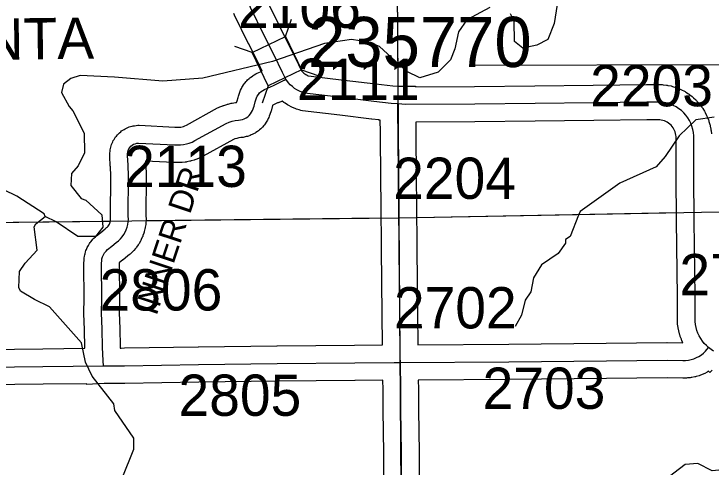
# Model space of a CAD drawing. Extents: x 23.6 to 68.7, y -63 to -29.
# Drawn here: x 41.141 to 42.324, y -56.084 to -55.315 of the extents above; entities that cross this region are included whole.
import ezdxf

# ---------------------------------------------------------------- set-up
doc = ezdxf.new("R2010")
doc.units = 0
for name, color, linetype in [('tdCoDirctArrow', 7, 'Continuous'), ('tdCoHydroRiver', 7, 'Continuous'), ('tdCoSecRdNmbr', 7, 'Continuous'), ('tdCoSecRdTxt', 7, 'Continuous'), ('tdCoSecRteBand', 7, 'Continuous'), ('tdCoSecRteCL', 7, 'Continuous'), ('tdCoSectLine', 7, 'Continuous'), ('tdCoSectLinePart', 7, 'Continuous'), ('tdCoStrucSec', 7, 'Continuous'), ('tdCoStrucSecFHWANum', 7, 'Continuous'), ('tdCoSurfGravel', 7, 'Continuous'), ('tdCoUnicrpTwnTxt', 7, 'Continuous')]:
    doc.layers.add(name, color=color, linetype=linetype)

msp = doc.modelspace()

# ---------------------------------------------------------------- linework, layer by layer
at = {"layer": 'tdCoDirctArrow'}
msp.add_lwpolyline([(41.919, -55.4023), (42.3403, -55.4012)], dxfattribs=at)
at = {"layer": 'tdCoHydroRiver'}
for points in [[(42.0696, -55.2557), (42.0577, -55.3316), (42.0469, -55.3586), (42.028, -55.3682), (42.0044, -55.3732), (41.9901, -55.3623), (41.9898, -55.3275), (41.9833, -55.315)], [(41.9485, -55.3043), (41.9092, -55.3252), (41.8952, -55.3458), (41.8892, -55.3743), (41.8815, -55.3933), (41.8611, -55.414), (41.8297, -55.4238), (41.8075, -55.4129), (41.7613, -55.3708), (41.7423, -55.363), (41.7138, -55.3586), (41.6681, -55.3653), (41.58, -55.3962), (41.4619, -55.4241), (41.394, -55.4295), (41.3119, -55.4224), (41.2535, -55.4198), (41.2377, -55.4247), (41.2252, -55.4343), (41.2222, -55.4485), (41.235, -55.4721), (41.2414, -55.4799), (41.2607, -55.5176), (41.261, -55.5507), (41.2502, -55.5729), (41.2392, -55.5857), (41.2379, -55.6062), (41.2554, -55.6281), (41.2634, -55.6312), (41.2904, -55.6562), (41.2922, -55.6767), (41.2797, -55.6926), (41.2497, -55.6929), (41.2132, -55.668), (41.1942, -55.6587)], [(42.3291, -55.4901), (42.2976, -55.4951), (42.2694, -55.5222), (42.2461, -55.5572), (42.2305, -55.5747), (42.1692, -55.6021), (42.1018, -55.6501), (42.0987, -55.6564), (42.0848, -55.6929), (42.0769, -55.6977), (42.077, -55.704), (42.0645, -55.7215), (42.0363, -55.7407), (42.0223, -55.7629), (42.0178, -55.7866), (42.0085, -55.8009), (42.0024, -55.8263), (41.9915, -55.8453)], [(41.1942, -55.6587), (41.1925, -55.654), (41.1465, -55.6244), (41.1243, -55.6136)], [(41.3247, -56.1026), (41.3447, -56.0535), (41.3445, -56.0346), (41.3125, -55.9875), (41.3108, -55.9765), (41.2741, -55.9295), (41.2628, -55.9059), (41.2562, -55.8728), (41.2019, -55.8118), (41.1765, -55.7994), (41.1527, -55.7854), (41.1495, -55.7791), (41.1508, -55.7523), (41.1602, -55.738), (41.1805, -55.7157), (41.1754, -55.6763), (41.1785, -55.6715), (41.1942, -55.6587)], [(42.8565, -55.9997), (42.8486, -56.0061), (42.8175, -56.0506), (42.8081, -56.0601), (42.783, -56.0714), (42.7561, -56.0717), (42.7037, -56.0327), (42.6452, -56.0222), (42.5205, -56.0313), (42.445, -56.051), (42.3963, -56.0798), (42.3758, -56.0848), (42.3254, -56.09), (42.3015, -56.0776), (42.2795, -56.0794), (42.2168, -56.1273), (42.1586, -56.1515), (42.1398, -56.1675), (42.129, -56.1897), (42.0827, -56.3007), (42.0765, -56.3118), (42.0644, -56.3671)]]:
    msp.add_lwpolyline(points, dxfattribs=at)
at = {"layer": 'tdCoSecRteBand'}
for points in [[(41.5708, -55.2938), (41.5926, -55.3384), (41.6095, -55.3718), (41.6096, -55.3721), (41.6098, -55.3723), (41.6237, -55.4012), (41.6292, -55.4118), (41.6293, -55.4119), (41.6296, -55.4123), (41.6311, -55.414), (41.6328, -55.4155), (41.6346, -55.4169), (41.6365, -55.4181), (41.6385, -55.4192), (41.6406, -55.4201), (41.641, -55.4202), (41.7011, -55.4274), (41.7012, -55.4274), (41.7013, -55.4274), (41.7549, -55.4341), (41.7837, -55.4372), (41.7937, -55.4379), (41.8224, -55.4378), (41.8224, -55.4389), (41.9227, -55.4385), (42.0248, -55.4372), (42.1239, -55.4359), (42.1239, -55.4359), (42.124, -55.4359), (42.2144, -55.4347), (42.2148, -55.4347), (42.2152, -55.4347), (42.2393, -55.4351), (42.241, -55.4351), (42.2426, -55.4353), (42.248, -55.4359), (42.2493, -55.4361), (42.2506, -55.4364), (42.2559, -55.4375), (42.2572, -55.4378), (42.2585, -55.4382), (42.2637, -55.4398), (42.265, -55.4402), (42.2662, -55.4408), (42.2712, -55.4428), (42.2725, -55.4433), (42.2737, -55.444), (42.2785, -55.4465), (42.2796, -55.4471), (42.2808, -55.4478), (42.2853, -55.4508), (42.2865, -55.4515), (42.2875, -55.4523), (42.2918, -55.4556), (42.2929, -55.4565), (42.2938, -55.4574), (42.2978, -55.4611), (42.2988, -55.462), (42.2997, -55.463), (42.3033, -55.4671), (42.3042, -55.4681), (42.305, -55.4692), (42.3082, -55.4735), (42.309, -55.4746), (42.3097, -55.4757), (42.3125, -55.4803), (42.3133, -55.4815), (42.3138, -55.4827), (42.3162, -55.4876), (42.3168, -55.4888), (42.3173, -55.49), (42.3193, -55.4951), (42.3198, -55.4963), (42.3201, -55.4976), (42.3216, -55.5028), (42.322, -55.5041), (42.3223, -55.5055), (42.3233, -55.5108), (42.3235, -55.5121), (42.3237, -55.5134), (42.3242, -55.5188)], [(41.0449, -55.8847), (41.1902, -55.8829), (41.1902, -55.8829), (41.1903, -55.8829), (41.2617, -55.8823), (41.2616, -55.8816), (41.2616, -55.8812), (41.2616, -55.8809), (41.2608, -55.8509), (41.2598, -55.8231), (41.2598, -55.8222), (41.2598, -55.8212), (41.2604, -55.7987), (41.2603, -55.7809), (41.2598, -55.7581), (41.2598, -55.7575), (41.2598, -55.7569), (41.2601, -55.7372), (41.2601, -55.7372), (41.2601, -55.7371), (41.2602, -55.7335), (41.2602, -55.7315), (41.2605, -55.7295), (41.2611, -55.7259), (41.2614, -55.7239), (41.2619, -55.722), (41.263, -55.7185), (41.2635, -55.7166), (41.2643, -55.7148), (41.2658, -55.7114), (41.2666, -55.7096), (41.2676, -55.7079), (41.2696, -55.7048), (41.2706, -55.7031), (41.2718, -55.7015), (41.2742, -55.6987), (41.2754, -55.6971), (41.2768, -55.6958), (41.2795, -55.6932), (41.2804, -55.6924), (41.2814, -55.6916), (41.2887, -55.6858), (41.2959, -55.6799), (41.296, -55.6798), (41.2961, -55.6797), (41.2986, -55.6777), (41.2999, -55.6763), (41.3012, -55.6749), (41.3022, -55.6734), (41.3032, -55.6717), (41.304, -55.67), (41.3046, -55.6683), (41.305, -55.6664), (41.3053, -55.6646), (41.3054, -55.6627), (41.3053, -55.6594), (41.3053, -55.6589), (41.3053, -55.6583), (41.3056, -55.591), (41.3049, -55.5733), (41.3048, -55.5733), (41.3048, -55.5732), (41.3042, -55.5564), (41.3042, -55.5561), (41.3042, -55.5558), (41.3041, -55.5529), (41.3041, -55.5507), (41.3044, -55.5486), (41.3047, -55.5458), (41.305, -55.5436), (41.3056, -55.5415), (41.3064, -55.5387), (41.307, -55.5366), (41.3079, -55.5346), (41.309, -55.532), (41.3099, -55.53), (41.3111, -55.5282), (41.3126, -55.5258), (41.3138, -55.5239), (41.3153, -55.5223), (41.3171, -55.5201), (41.3185, -55.5185), (41.3202, -55.517), (41.3224, -55.5152), (41.324, -55.5138), (41.3259, -55.5126), (41.3283, -55.5111), (41.3301, -55.5099), (41.3322, -55.509), (41.3347, -55.5079), (41.3368, -55.507), (41.3389, -55.5064), (41.3416, -55.5056), (41.3437, -55.505), (41.3459, -55.5048), (41.3487, -55.5044), (41.3513, -55.5041), (41.3539, -55.5042), (41.4142, -55.5073), (41.4222, -55.5073), (41.4243, -55.5071), (41.4267, -55.5066), (41.429, -55.506), (41.4312, -55.5051), (41.434, -55.5037), (41.4868, -55.4747), (41.4885, -55.4737), (41.4903, -55.473), (41.4954, -55.4711), (41.4963, -55.4707), (41.4973, -55.4704), (41.5025, -55.4688), (41.5035, -55.4684), (41.5045, -55.4682), (41.5097, -55.4669), (41.5107, -55.4667), (41.5117, -55.4665), (41.5171, -55.4656), (41.5182, -55.4655), (41.519, -55.4654), (41.5199, -55.4627), (41.5216, -55.4569), (41.5221, -55.4546), (41.5225, -55.4528), (41.5231, -55.4511), (41.5242, -55.4479), (41.5248, -55.4462), (41.5256, -55.4445), (41.5271, -55.4415), (41.5279, -55.4399), (41.5289, -55.4383), (41.5308, -55.4355), (41.5318, -55.4339), (41.5329, -55.4325), (41.5351, -55.4299), (41.5363, -55.4285), (41.5376, -55.4273), (41.5401, -55.425), (41.5415, -55.4237), (41.5429, -55.4227), (41.5457, -55.4207), (41.5472, -55.4196), (41.5488, -55.4187), (41.5517, -55.417), (41.5528, -55.4164), (41.5539, -55.4159), (41.5623, -55.4121), (41.5559, -55.3987), (41.5389, -55.3654), (41.5388, -55.3652), (41.5387, -55.3649), (41.5155, -55.3174), (41.5142, -55.3147)], [(41.3217, -55.8818), (41.323, -55.8818), (41.3287, -55.8817), (41.4539, -55.8795), (41.454, -55.8795), (41.4541, -55.8795), (41.5875, -55.878), (41.5875, -55.878), (41.5876, -55.878), (41.7192, -55.877), (41.7664, -55.8765), (41.7658, -55.8252), (41.7658, -55.8252), (41.7658, -55.8252), (41.7648, -55.7135), (41.7648, -55.7135), (41.7648, -55.7134), (41.7643, -55.6367), (41.7637, -55.598), (41.7637, -55.5979), (41.7637, -55.5978), (41.7629, -55.5156), (41.7629, -55.5156), (41.7629, -55.5155), (41.7627, -55.4957), (41.7603, -55.4955), (41.7604, -55.495), (41.7483, -55.4937), (41.748, -55.4937), (41.7477, -55.4937), (41.6939, -55.487), (41.6308, -55.4794), (41.6278, -55.479), (41.6249, -55.4781), (41.6204, -55.4766), (41.6192, -55.4762), (41.6181, -55.4757), (41.6138, -55.4738), (41.6126, -55.4733), (41.6115, -55.4728), (41.6074, -55.4705), (41.6063, -55.47), (41.6052, -55.4693), (41.6012, -55.4668), (41.6002, -55.4661), (41.5992, -55.4653), (41.5962, -55.463), (41.5898, -55.4663), (41.5895, -55.4657), (41.5802, -55.4699), (41.58, -55.4707), (41.5798, -55.4717), (41.5795, -55.4727), (41.5774, -55.4801), (41.5772, -55.4807), (41.577, -55.4813), (41.5745, -55.4886), (41.5738, -55.4907), (41.5728, -55.4926), (41.5712, -55.4957), (41.5704, -55.4973), (41.5693, -55.4989), (41.5674, -55.5017), (41.5663, -55.5032), (41.5651, -55.5047), (41.5628, -55.5072), (41.5616, -55.5086), (41.5602, -55.5099), (41.5576, -55.5121), (41.5562, -55.5133), (41.5547, -55.5144), (41.5518, -55.5163), (41.5503, -55.5174), (41.5486, -55.5182), (41.5456, -55.5198), (41.5439, -55.5206), (41.5421, -55.5212), (41.5389, -55.5224), (41.5372, -55.523), (41.5353, -55.5234), (41.532, -55.5242), (41.5302, -55.5246), (41.5283, -55.5248), (41.526, -55.525), (41.5227, -55.5255), (41.5194, -55.5263), (41.5162, -55.5273), (41.5139, -55.5282), (41.4624, -55.5565), (41.4619, -55.5568), (41.4614, -55.5571), (41.4568, -55.5593), (41.4556, -55.5599), (41.4544, -55.5604), (41.4496, -55.5623), (41.4484, -55.5628), (41.4471, -55.5632), (41.4422, -55.5646), (41.4409, -55.565), (41.4396, -55.5652), (41.4346, -55.5662), (41.4333, -55.5665), (41.432, -55.5666), (41.4269, -55.5671), (41.4253, -55.5673), (41.4238, -55.5673), (41.4134, -55.5673), (41.4126, -55.5673), (41.4119, -55.5673), (41.3646, -55.5648), (41.3648, -55.5707), (41.3656, -55.5891), (41.3656, -55.5898), (41.3656, -55.5906), (41.3653, -55.6581), (41.3654, -55.6622), (41.3655, -55.6635), (41.3654, -55.6649), (41.3651, -55.6696), (41.365, -55.6709), (41.3648, -55.6723), (41.3641, -55.6769), (41.3639, -55.6783), (41.3636, -55.6796), (41.3625, -55.6841), (41.3621, -55.6855), (41.3617, -55.6868), (41.3601, -55.6912), (41.3597, -55.6925), (41.3591, -55.6937), (41.3572, -55.698), (41.3566, -55.6992), (41.3559, -55.7004), (41.3536, -55.7045), (41.3529, -55.7057), (41.3521, -55.7068), (41.3494, -55.7106), (41.3486, -55.7117), (41.3477, -55.7128), (41.3447, -55.7163), (41.3438, -55.7174), (41.3428, -55.7183), (41.3395, -55.7216), (41.3385, -55.7226), (41.3374, -55.7234), (41.3339, -55.7263), (41.3266, -55.7322), (41.3265, -55.7324), (41.3263, -55.7325), (41.3201, -55.7375), (41.3201, -55.7383), (41.3198, -55.7574), (41.3203, -55.7798), (41.3203, -55.78), (41.3203, -55.7802), (41.3204, -55.7988), (41.3204, -55.7993), (41.3204, -55.7999), (41.3198, -55.822), (41.3207, -55.8489), (41.3207, -55.8491), (41.3208, -55.8492), (41.3216, -55.8789), (41.3217, -55.8818)], [(41.8266, -55.8761), (41.9807, -55.8753), (42.1458, -55.8736), (42.1458, -55.8736), (42.1458, -55.8736), (42.2487, -55.8726), (42.249, -55.8726), (42.2492, -55.8726), (42.2758, -55.8728), (42.2759, -55.8728), (42.2742, -55.8692), (42.2737, -55.8681), (42.2733, -55.867), (42.2715, -55.8622), (42.2711, -55.861), (42.2708, -55.8598), (42.2694, -55.8549), (42.2691, -55.8537), (42.2688, -55.8525), (42.2679, -55.8475), (42.2677, -55.8463), (42.2675, -55.8451), (42.267, -55.84), (42.2668, -55.8385), (42.2668, -55.837), (42.2665, -55.7948), (42.2653, -55.6656), (42.2653, -55.6656), (42.2653, -55.6656), (42.2647, -55.5904), (42.2647, -55.5904), (42.2647, -55.5903), (42.2643, -55.5233), (42.2641, -55.5207), (42.2636, -55.518), (42.2628, -55.5154), (42.2618, -55.5129), (42.2607, -55.5105), (42.2592, -55.5082), (42.2576, -55.506), (42.2558, -55.504), (42.2538, -55.5021), (42.2517, -55.5005), (42.2494, -55.499), (42.247, -55.4977), (42.2445, -55.4967), (42.2419, -55.4959), (42.2393, -55.4953), (42.2369, -55.495), (42.2147, -55.4947), (42.1247, -55.4959), (42.0256, -55.4972), (42.0256, -55.4972), (42.0256, -55.4972), (41.9233, -55.4985), (41.9232, -55.4985), (41.9231, -55.4985), (41.8228, -55.4989), (41.8229, -55.5151), (41.8237, -55.5971), (41.8243, -55.6358), (41.8243, -55.636), (41.8243, -55.6361), (41.8248, -55.713), (41.8258, -55.8246), (41.8264, -55.8761), (41.8266, -55.8761), (41.8266, -55.8761)], [(42.3254, -55.9194), (42.3217, -55.9235), (42.3193, -55.9213), (42.3184, -55.9218), (42.3171, -55.9225), (42.3129, -55.9247), (42.3117, -55.9254), (42.3104, -55.9259), (42.306, -55.9277), (42.3046, -55.9282), (42.3033, -55.9287), (42.2987, -55.93), (42.2974, -55.9305), (42.296, -55.9307), (42.2913, -55.9317), (42.2899, -55.932), (42.2885, -55.9321), (42.2837, -55.9326), (42.2823, -55.9328), (42.2809, -55.9328), (42.2761, -55.9328), (42.2759, -55.9328), (42.2756, -55.9328), (42.249, -55.9326), (42.1464, -55.9336), (41.9812, -55.9353), (41.9811, -55.9353), (41.9811, -55.9353), (41.8271, -55.9361), (41.8273, -55.9509), (41.8273, -55.9511), (41.8273, -55.9512), (41.8275, -55.987), (41.8286, -56.0587), (41.8286, -56.0589), (41.8286, -56.0591), (41.8288, -56.1617)], [(41.7688, -56.162), (41.7686, -56.0594), (41.7675, -55.9878), (41.7675, -55.9876), (41.7675, -55.9875), (41.7673, -55.9516), (41.7671, -55.9366), (41.7671, -55.9365), (41.7198, -55.937), (41.7198, -55.937), (41.7197, -55.937), (41.5881, -55.938), (41.4548, -55.9395), (41.3297, -55.9417), (41.3295, -55.9417), (41.3294, -55.9417), (41.2942, -55.942), (41.265, -55.9437), (41.2649, -55.9423), (41.1908, -55.9429), (41.0456, -55.9447)]]:
    msp.add_lwpolyline(points, dxfattribs=at)
at = {"layer": 'tdCoSecRteCL'}
for points in [[(41.6027, -55.4258), (41.5969, -55.4147), (41.5827, -55.3854), (41.5657, -55.3518), (41.5425, -55.3043), (41.5411, -55.2987), (41.54, -55.2931), (41.5392, -55.2873), (41.5389, -55.2816), (41.5384, -55.2625), (41.5377, -55.1637), (41.5375, -55.132), (41.5368, -55.0514), (41.5363, -54.9354), (41.5353, -54.8221), (41.5348, -54.8083), (41.5343, -54.7323), (41.5317, -54.6811), (41.53, -54.6573)], [(41.2932, -55.912), (41.2927, -55.9033), (41.2916, -55.8801), (41.2908, -55.85), (41.2898, -55.8221), (41.2904, -55.799), (41.2903, -55.7805), (41.2898, -55.7574), (41.2901, -55.7377), (41.2902, -55.734), (41.2907, -55.7304), (41.2918, -55.7269), (41.2932, -55.7235), (41.2952, -55.7204), (41.2975, -55.7176), (41.3001, -55.715), (41.3076, -55.7091), (41.3149, -55.703), (41.3185, -55.7001), (41.3219, -55.6969), (41.3249, -55.6933), (41.3276, -55.6895), (41.3299, -55.6855), (41.3318, -55.6813), (41.3334, -55.6769), (41.3345, -55.6724), (41.3352, -55.6678), (41.3355, -55.6631), (41.3353, -55.6585), (41.3356, -55.5904), (41.3348, -55.572), (41.3342, -55.5552), (41.3341, -55.5524), (41.3345, -55.5496), (41.3352, -55.5469), (41.3364, -55.5443), (41.3379, -55.5419), (41.3398, -55.5398), (41.3419, -55.5379), (41.3443, -55.5364), (41.3469, -55.5353), (41.3496, -55.5345), (41.3524, -55.5342), (41.4134, -55.5373), (41.4238, -55.5373), (41.4288, -55.5368), (41.4338, -55.5358), (41.4387, -55.5344), (41.4434, -55.5325), (41.4479, -55.5302), (41.5012, -55.501), (41.5063, -55.499), (41.5114, -55.4974), (41.5167, -55.4961), (41.5221, -55.4952), (41.5255, -55.4949), (41.5288, -55.4942), (41.532, -55.493), (41.535, -55.4915), (41.5378, -55.4896), (41.5404, -55.4873), (41.5426, -55.4848), (41.5445, -55.482), (41.5461, -55.4789), (41.5485, -55.4717), (41.5507, -55.4643), (41.5514, -55.461), (41.5525, -55.4578), (41.554, -55.4547), (41.5559, -55.4519), (41.5581, -55.4493), (41.5606, -55.4469), (41.5633, -55.4449), (41.5663, -55.4433), (41.5813, -55.4365), (41.5961, -55.4293), (41.5994, -55.4276), (41.6027, -55.4258)], [(41.7926, -55.468), (41.7809, -55.467), (41.7515, -55.4639), (41.6975, -55.4572), (41.6344, -55.4496), (41.6299, -55.4481), (41.6256, -55.4462), (41.6214, -55.444), (41.6174, -55.4415), (41.6137, -55.4386), (41.6101, -55.4355), (41.6069, -55.432), (41.604, -55.4283), (41.6027, -55.4258)], [(42.3195, -55.8811), (42.3157, -55.8777), (42.3122, -55.874), (42.309, -55.87), (42.3061, -55.8657), (42.3036, -55.8613), (42.3014, -55.8566), (42.2997, -55.8518), (42.2983, -55.8469), (42.2974, -55.8419), (42.2968, -55.8368), (42.2965, -55.7945), (42.2953, -55.6653), (42.2947, -55.5902), (42.2943, -55.5218), (42.2938, -55.5164), (42.2928, -55.5111), (42.2913, -55.5059), (42.2893, -55.5008), (42.287, -55.496), (42.2841, -55.4914), (42.2809, -55.487), (42.2773, -55.483), (42.2734, -55.4793), (42.2691, -55.476), (42.2645, -55.4731), (42.2597, -55.4705), (42.2547, -55.4685), (42.2496, -55.4669), (42.2443, -55.4657), (42.2389, -55.4651), (42.2148, -55.4647), (42.1243, -55.4659), (42.0252, -55.4672), (41.9229, -55.4685), (41.8061, -55.469), (41.7926, -55.468)], [(41.7967, -55.9062), (41.7966, -55.8977), (41.7958, -55.8249), (41.7948, -55.7133), (41.7943, -55.6363), (41.7937, -55.5975), (41.7929, -55.5153), (41.7927, -55.4883), (41.7926, -55.468)], [(41.7967, -55.9062), (41.9809, -55.9053), (42.1461, -55.9036), (42.249, -55.9026), (42.2758, -55.9028), (42.2806, -55.9028), (42.2853, -55.9023), (42.29, -55.9013), (42.2946, -55.8999), (42.299, -55.8981), (42.3032, -55.8959), (42.3072, -55.8933), (42.3109, -55.8903), (42.3143, -55.887), (42.3195, -55.8811)], [(42.3281, -55.8873), (42.3237, -55.8844), (42.3195, -55.8811)], [(40.7916, -55.9173), (40.9032, -55.9161), (41.0453, -55.9147), (41.1905, -55.9129), (41.2932, -55.912)], [(41.2932, -55.912), (41.3291, -55.9117), (41.4544, -55.9095), (41.5878, -55.908), (41.7195, -55.907), (41.7861, -55.9063), (41.7967, -55.9062)], [(41.8165, -57.6606), (41.8149, -57.6473), (41.8134, -57.5906), (41.8119, -57.4993), (41.8109, -57.3895), (41.809, -57.279), (41.807, -57.1595), (41.8057, -57.0602), (41.8049, -56.956), (41.8045, -56.8532), (41.8032, -56.7225), (41.803, -56.6609), (41.8029, -56.6428), (41.8024, -56.5966), (41.8012, -56.495), (41.8004, -56.3743), (41.8001, -56.2883), (41.7988, -56.1619), (41.7986, -56.0592), (41.7975, -55.9873), (41.7973, -55.9513), (41.7967, -55.9062)]]:
    msp.add_lwpolyline(points, dxfattribs=at)
at = {"layer": 'tdCoSectLine'}
for points in [[(41.787, -54.6536), (41.7942, -55.6609)], [(41.7942, -55.6609), (42.791, -55.6424)], [(40.787, -55.6724), (41.7942, -55.6609)], [(41.7942, -55.6609), (41.8014, -56.6545)]]:
    msp.add_lwpolyline(points, dxfattribs=at)
at = {"layer": 'tdCoSectLinePart'}
for points in [[(41.7872, -54.6832), (41.7926, -55.4377)], [(41.8239, -55.6603), (42.2649, -55.6522)], [(41.3649, -55.6658), (41.7642, -55.6612)], [(40.787, -55.6724), (41.3045, -55.6665)]]:
    msp.add_lwpolyline(points, dxfattribs=at)
at = {"layer": 'tdCoStrucSec'}
for p, q in [((41.6018, -55.3537), (41.6121, -55.3242)), ((41.5455, -55.381), (41.5159, -55.3708)), ((41.6291, -55.4101), (41.6587, -55.4203)), ((41.5728, -55.4374), (41.5625, -55.4669))]:
    msp.add_line(p, q, dxfattribs=at)
msp.add_lwpolyline([(41.5728, -55.4374), (41.5455, -55.381), (41.6018, -55.3537), (41.6291, -55.4101)], close=True, dxfattribs=at)
at = {"layer": 'tdCoSurfGravel'}
for points in [[(41.6027, -55.4258), (41.5969, -55.4147), (41.5827, -55.3854), (41.5657, -55.3518), (41.5425, -55.3043), (41.5411, -55.2987), (41.54, -55.2931), (41.5392, -55.2873), (41.5389, -55.2816), (41.5384, -55.2625), (41.5377, -55.1637), (41.5375, -55.132)], [(41.3353, -55.6585), (41.3356, -55.5904), (41.3348, -55.572), (41.3342, -55.5552), (41.3341, -55.5524), (41.3345, -55.5496), (41.3352, -55.5469), (41.3364, -55.5443), (41.3379, -55.5419), (41.3398, -55.5398), (41.3419, -55.5379), (41.3443, -55.5364), (41.3469, -55.5353), (41.3496, -55.5345), (41.3524, -55.5342), (41.4134, -55.5373), (41.4238, -55.5373), (41.4288, -55.5368), (41.4338, -55.5358), (41.4387, -55.5344), (41.4434, -55.5325), (41.4479, -55.5302), (41.5012, -55.501), (41.5063, -55.499), (41.5114, -55.4974), (41.5167, -55.4961), (41.5221, -55.4952), (41.5255, -55.4949), (41.5288, -55.4942), (41.532, -55.493), (41.535, -55.4915), (41.5378, -55.4896), (41.5404, -55.4873), (41.5426, -55.4848), (41.5445, -55.482), (41.5461, -55.4789), (41.5485, -55.4717), (41.5507, -55.4643), (41.5514, -55.461), (41.5525, -55.4578), (41.554, -55.4547), (41.5559, -55.4519), (41.5581, -55.4493), (41.5606, -55.4469), (41.5633, -55.4449), (41.5663, -55.4433), (41.5813, -55.4365), (41.5961, -55.4293), (41.5994, -55.4276), (41.6027, -55.4258)], [(42.3281, -55.8873), (42.3237, -55.8844), (42.3195, -55.8811), (42.3157, -55.8777), (42.3122, -55.874), (42.309, -55.87), (42.3061, -55.8657), (42.3036, -55.8613), (42.3014, -55.8566), (42.2997, -55.8518), (42.2983, -55.8469), (42.2974, -55.8419), (42.2968, -55.8368), (42.2965, -55.7945), (42.2953, -55.6653), (42.2947, -55.5902), (42.2943, -55.5218), (42.2938, -55.5164), (42.2928, -55.5111), (42.2913, -55.5059), (42.2893, -55.5008), (42.287, -55.496), (42.2841, -55.4914), (42.2809, -55.487), (42.2773, -55.483), (42.2734, -55.4793), (42.2691, -55.476), (42.2645, -55.4731), (42.2597, -55.4705), (42.2547, -55.4685), (42.2496, -55.4669), (42.2443, -55.4657), (42.2389, -55.4651), (42.2148, -55.4647), (42.1243, -55.4659), (42.0252, -55.4672), (41.9229, -55.4685), (41.8061, -55.469), (41.7926, -55.468), (41.7809, -55.467), (41.7515, -55.4639), (41.6975, -55.4572), (41.6344, -55.4496), (41.6299, -55.4481), (41.6256, -55.4462), (41.6214, -55.444), (41.6174, -55.4415), (41.6137, -55.4386), (41.6101, -55.4355), (41.6069, -55.432), (41.604, -55.4283), (41.6027, -55.4258)], [(41.7967, -55.9062), (41.7966, -55.8977), (41.7958, -55.8249), (41.7948, -55.7133), (41.7943, -55.6363), (41.7937, -55.5975), (41.7929, -55.5153), (41.7927, -55.4883), (41.7926, -55.468)], [(41.2932, -55.912), (41.2927, -55.9033), (41.2916, -55.8801), (41.2908, -55.85), (41.2898, -55.8221), (41.2904, -55.799), (41.2903, -55.7805), (41.2898, -55.7574), (41.2901, -55.7377), (41.2902, -55.734), (41.2907, -55.7304), (41.2918, -55.7269), (41.2932, -55.7235), (41.2952, -55.7204), (41.2975, -55.7176), (41.3001, -55.715), (41.3076, -55.7091), (41.3149, -55.703), (41.3185, -55.7001), (41.3219, -55.6969), (41.3249, -55.6933), (41.3276, -55.6895), (41.3299, -55.6855), (41.3318, -55.6813), (41.3334, -55.6769), (41.3345, -55.6724), (41.3352, -55.6678), (41.3355, -55.6631), (41.3353, -55.6585), (41.3353, -55.6585)], [(41.0453, -55.9147), (41.1905, -55.9129), (41.2932, -55.912), (41.3291, -55.9117), (41.4544, -55.9095), (41.5878, -55.908), (41.7195, -55.907), (41.7861, -55.9063), (41.7967, -55.9062), (41.9809, -55.9053), (42.1461, -55.9036), (42.249, -55.9026), (42.2758, -55.9028), (42.2806, -55.9028), (42.2853, -55.9023), (42.29, -55.9013), (42.2946, -55.8999), (42.299, -55.8981), (42.3032, -55.8959), (42.3072, -55.8933), (42.3109, -55.8903), (42.3143, -55.887), (42.3195, -55.8811)], [(41.803, -56.6609), (41.8029, -56.6428), (41.8024, -56.5966), (41.8012, -56.495), (41.8004, -56.3743), (41.8001, -56.2883), (41.7988, -56.1619), (41.7986, -56.0592), (41.7975, -55.9873), (41.7973, -55.9513), (41.7967, -55.9062), (41.7967, -55.9062)]]:
    msp.add_lwpolyline(points, dxfattribs=at)

# ---------------------------------------------------------------- texts
at = {"layer": 'tdCoSecRdNmbr'}
for s, rotation, p in [('2106', 0.0324, (41.5215, -55.339)), ('2111', 0.0325, (41.6214, -55.4611)), ('2203', 0.0328, (42.1187, -55.472)), ('2113', 0.0322, (41.3282, -55.6088)), ('2204', 0.0326, (41.7846, -55.629)), ('2706', 0.0329, (42.27, -55.7924)), ('2806', 0.0322, (41.2866, -55.8182)), ('2702', 0.0326, (41.7858, -55.8486)), ('2703', 0.0327, (41.9362, -55.985)), ('2805', 0.0323, (41.4205, -55.9968))]:
    msp.add_text(s, height=0.07, rotation=rotation, dxfattribs=at).set_placement(p)
at = {"layer": 'tdCoSecRdTxt'}
msp.add_text('INNER DR', height=0.04, rotation=71.7397, dxfattribs=at).set_placement((41.383, -55.8285))
at = {"layer": 'tdCoStrucSecFHWANum'}
msp.add_text('235770', height=0.085, dxfattribs=at).set_placement((41.6402, -55.4053))
at = {"layer": 'tdCoUnicrpTwnTxt'}
msp.add_text('LAKONTA', height=0.07, rotation=0.7838, dxfattribs=at).set_placement((40.8406, -55.397))

doc.saveas('drawing.dxf')
